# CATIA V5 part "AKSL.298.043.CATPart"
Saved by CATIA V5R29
Part number: АКСЛ.298.043
Definition: Уголок 200 мм
Publications: "Грань по длине шипа", "Грань по ширине шипа"
Material "Steel": density 7860 kg/m3, Young's modulus 2e+11 Pa, Poisson ratio 0.266, thermal expansion 1.17e-05 1/K
Bounding box of the stored display mesh (mm): x -52 to 51, y -52 to 51, z -98 to 98
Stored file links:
  Z:\ООО Аксель\Соединения бруса\Соединения бруса\Соединения из листа\АКСЛ.298.040 (Кватро)\AKSL.298.043.CATPart
  Z:\ООО Аксель\Соединения бруса\Соединения бруса\Соединения из листа\АКСЛ.298.040 (Кватро)\AKSL.298.040.CATProduct
  Z:\#Catalog_GosNIIAS\Holes&Pockets\Part\Соединение шип-паз\Ship-Paz.CATPart
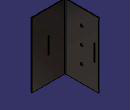
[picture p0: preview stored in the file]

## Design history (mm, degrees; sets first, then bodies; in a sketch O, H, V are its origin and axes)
External parameters (linked from other documents)
  `External.S металла` = 2 mm
  `External.R гиба` = 1.9 mm
  `External.K factor` = 0.49
SheetMetalParameters1: Thickness 2 {= `External.S металла`}, BendRadius 1.9 {= `External.R гиба`}, KFactor 0.49 {= `External.K factor`}, ReliefRadialLength 1, ReliefAxialLength 2, MinimumBendRadius 0
Set1 "Шип в центре грани"
  Extract1 "Плоскость шипа": ExtractElem face of Wall1
  Extract2 "Грань по длине шипа": ExtractElem edge of Extract1
  Extract3 "Грань по ширине шипа": ExtractElem edge of Extract1
Set2
  DatumSurface1: linked copy from another document
  DatumCurve1 to DatumCurve6: linked copy from another document
Body1 (main body)
  ThickSurface1: BotOffset 0, Surface DatumSurface1, TopOffset 2 {= `External.S металла`}
  Recognize1: Recognize_BendTable SheetMetalParameters1, Recognize_ReferenceFace face of ThickSurface1, Recognize_BendDefaultRadius 1.9 {= `External.R гиба`}, KFacteur 0.49 {= SheetMetalParameters1.KFactor}
  d_Bend1: Bend_BendTable SheetMetalParameters1, Bend_Thickness 2 {= `External.S металла`}, Bend_KFactor 0.49 {= SheetMetalParameters1.KFactor}, Bend_FirstSupport face of Recognize1, Bend_SecondSupport face of Recognize1, Bend_KFactorRadius 1.9 {= d_Bend1.CylindricalBendSurf_Radius}, Bend_Deduction -3.2761 {= (d_Bend1.CylindricalBendSurf_Radius+SheetMetalParameters1.Thickness*d_Bend1.Bend_KFactor)*(PI-abs(d_Bend1.BendSurf_OpenAngle))-2*(d_Bend1.CylindricalBendSurf_Radius+SheetMetalParameters1.Thickness)*tan(min((PI-abs(d_Bend1.BendSurf_OpenAngle)),(PI/2))/2)}
  Sketch1 on face of Recognize1, origin (-52, -17.9496, -74.4009), H (0, 1, 0), V (0, 0, -1)
    point P1 (17.9496, -26.4009)
    reference projected line E1 (-34.0504, 23.5991) -> (-34.0504, -172.4009) from face of Recognize1
    reference projected line E2 (69.9496, 23.5991) -> (69.9496, -172.4009) from edge [face of Recognize1 | face of Recognize1]
    reference projected line E3 (69.9496, 23.5991) -> (-30.1504, 23.5991) from edge [face of Recognize1 | face of Recognize1]
    distance P1 E3 = 50
    equidistance: E2 E1 P1
  Hole1: placed by Sketch1, at (-52, 0, -48) direction (1, 0, 0), diameter 8, through (limit type 6)
  RectPattern1: of Hole1, direction 1 instances 3, spacing 50, along edge [face of Recognize1 | face of Recognize1]
  CutOut1: Direction Sketch2, EndLimit through (limit type 2), Orientation true, Profile Sketch2, StartLimit through (limit type 2)
  CutOut2: Direction Sketch3, EndLimit through (limit type 2), Orientation true, Profile Sketch3, StartLimit through (limit type 2)
  Wall1: Thickness 2 {= `External.S металла`}, Profile Sketch4, ListTangentTo face of Recognize1, OffsetValue 0
  CutOut3: Direction Sketch5, EndLimit through (limit type 2), Orientation true, Profile Sketch5, StartLimit through (limit type 2)
  Sketch2 on DatumCurve1, origin (-1.5, -50, -23.9612), H (0, 0, 1), V (-1, 0, 0)
    reference projected line E1 (0, -3) -> (0, 0) from DatumCurve2
    reference projected line E2 (0, 0) -> (50, 0) from DatumCurve1
    construction line L1 (0, -1.5) -> (25, -1.5)
    point P5 (0, -1.5)
    point P6 (25, -1.5)
    axis line L2 (25, 0) -> (25, 7.3468)
    point P7 (25, 0)
    line L3 (50.1, -3.1) -> (50.1, 0.1)
    line L4 (50.1, 0.1) -> (-0.1, 0.1)
    line L5 (-0.1, 0.1) -> (-0.1, -3.1)
    line L6 (-0.1, -3.1) -> (50.1, -3.1)
    distance L5 E1 = 0.1
    distance E2 L4 = 0.1
    midpoint: P5 E1, P7 E2
    coincidence: L2 P6
    equidistance: L3 L5 P6, L4 L6 P6
    parallelism: L1 E2, L2 E1, L6 L4, L3 L5
  Sketch3 on DatumCurve3, origin (-50, 37, 26.0388), H (0, 0, -1), V (0, -1, 0)
    reference projected line E1 (0, -3) -> (0, 0) from DatumCurve4
    reference projected line E2 (0, 0) -> (50, 0) from DatumCurve3
    construction line L1 (0, -1.5) -> (25, -1.5)
    point P5 (0, -1.5)
    point P6 (25, -1.5)
    axis line L2 (25, 0) -> (25, 7.3468)
    point P7 (25, 0)
    line L3 (50.1, -3.1) -> (50.1, 0.1)
    line L4 (50.1, 0.1) -> (-0.1, 0.1)
    line L5 (-0.1, 0.1) -> (-0.1, -3.1)
    line L6 (-0.1, -3.1) -> (50.1, -3.1)
    distance L5 E1 = 0.1
    distance E2 L4 = 0.1
    midpoint: P5 E1, P7 E2
    coincidence: L2 P6
    equidistance: L3 L5 P6, L4 L6 P6
    parallelism: L1 E2, L2 E1, L6 L4, L3 L5
  Sketch4 on face of Recognize1, origin (-52, -52, 0), H (1, 0, 0), V (0, 0, 1)
    reference projected line E1 (102, 98) -> (102, -98) from edge [face of Recognize1 | face of Recognize1]
    line L1 (103, -90) -> (102, -90)
    line L2 (102, -90) -> (102, 90)
    line L3 (102, 90) -> (103, 90)
    line L4 (103, 90) -> (103, -90)
    axis line L5 (102, 0) -> (103, 0)
    point P7 (102, 0)
    point P8 (103, 0)
    distance L2 L4 = 1 {= `External.S металла` /2}
    distance L1 L3 = 180
    length E1 = 196 (reference)
    perpendicularity: L2 L1
    midpoint: P7 L2, P8 L4, P7 E1
    coincidence: L2 E1
  Sketch5 on DatumCurve5, origin (-51, 50, 90), H (0, 0, 1), V (0, 1, 0)
    reference projected line E1 (0, 0) -> (0, 2) from DatumCurve6
    reference projected line E2 (-180, 0) -> (0, 0) from DatumCurve5
    construction line L1 (0, 1) -> (-90, 1)
    point P5 (0, 1)
    point P6 (-90, 1)
    axis line L2 (-90, 0) -> (-90, 7.3468)
    point P7 (-90, 0)
    line L3 (-180.5, 2) -> (-180.5, 0)
    line L4 (-180.5, 0) -> (0.5, 0)
    line L5 (0.5, 0) -> (0.5, 2)
    line L6 (0.5, 2) -> (-180.5, 2)
    distance L5 E1 = 0.5
    distance E2 L4 = 0
    midpoint: P5 E1, P7 E2
    coincidence: L2 P6
    equidistance: L3 L5 P6, L4 L6 P6
    parallelism: L1 E2, L2 E1, L6 L4, L3 L5
  Sketch6 on face of Recognize1, origin (-52, 0, 0), H (0, -1, 0), V (0, 0, 1)
    reference projected line E2 (-52, -98) -> (48.1, -98) from edge [face of Recognize1 | face of Recognize1]
    reference projected line E5 (-50, 90.5) -> (-52, 90.5) from edge [face of Recognize1 | face of CutOut3]
    line L1 (-52, 98) -> (-51, 98)
    line L2 (-51, 98) -> (-51, 90.5)
    line L3 (-51, 90.5) -> (-52, 90.5)
    line L4 (-52, 90.5) -> (-52, 98)
    point P12 (-51, 90.5)
    line L5 (-52, -90.5) -> (-51, -90.5)
    line L6 (-51, -90.5) -> (-51, -98)
    line L7 (-51, -98) -> (-52, -98)
    line L8 (-52, -98) -> (-52, -90.5)
    distance L6 L8 = 1 {= `External.S металла` /2}
    horizontal: L1 H, L3 H, L5 H, L7 H
    vertical: L2 V, L4 V, L6 V, L8 V
    midpoint: P12 E5
    coincidence: L7 E2
  CutOut4: Direction Sketch6, EndLimit through (limit type 2), Orientation true, StartLimit through (limit type 2), Profile Sketch6, Thickness1 2, Thickness2 2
